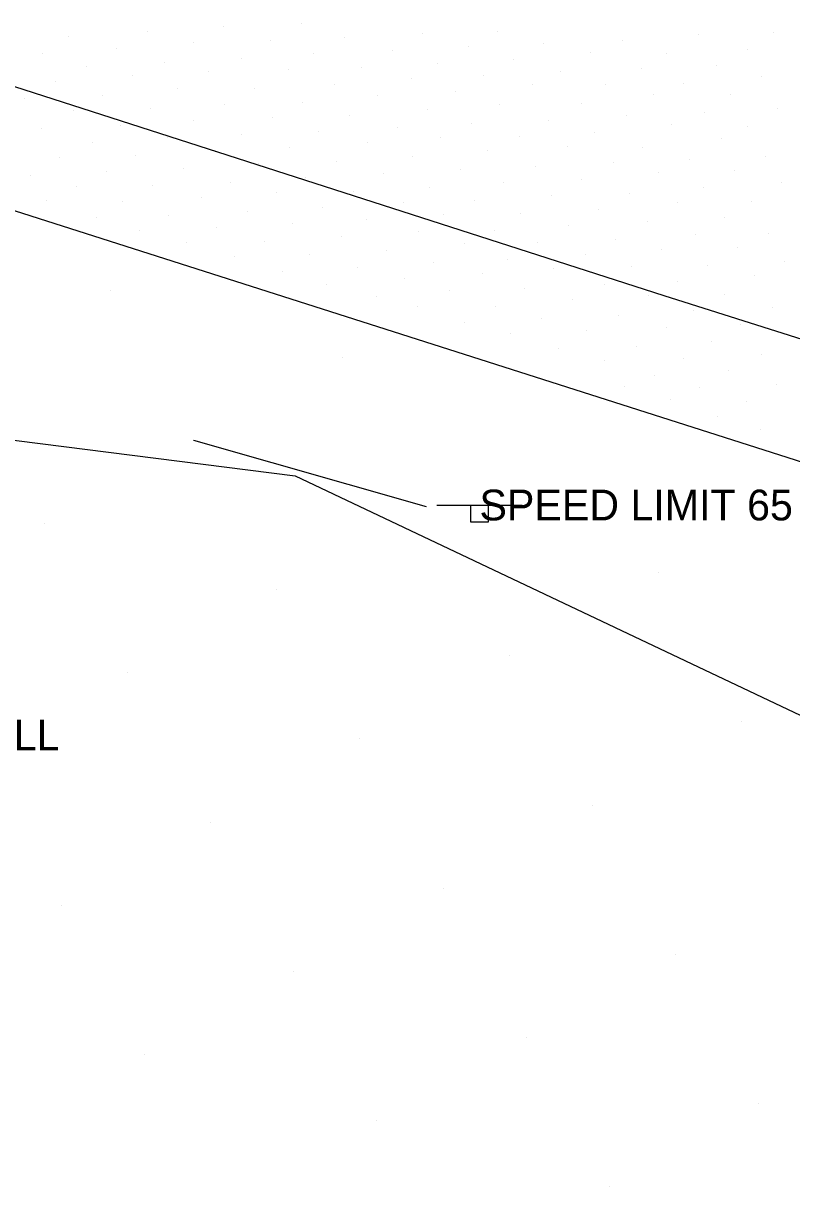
# Model space of a CAD drawing. Extents: x 1733582 to 1734070, y 467256 to 468256.
# Drawn here: x 1733871.5 to 1733916.4, y 467626.2 to 467694.3 of the extents above; entities that cross this region are included whole.
import ezdxf

# ---------------------------------------------------------------- set-up
doc = ezdxf.new("R2010")
doc.units = 0
for name, color, linetype in [('Default', 7, 'Continuous'), ('S_Ground_LevelString', 7, 'Continuous'), ('S_Ground_SpotElevation', 7, 'Continuous'), ('S_Roadway_Edge_Pavement', 7, 'Continuous'), ('S_Roadway_Painted_Lines', 7, 'Continuous'), ('S_Text', 7, 'Continuous'), ('S_Traffic_Sign_SinglePost', 7, 'Continuous'), ('S_Trees_Bush_Line', 7, 'Continuous')]:
    doc.layers.add(name, color=color, linetype=linetype)

# ---------------------------------------------------------------- blocks, each defined once
blk = doc.blocks.new('POINT_DISPLAY')
at = {"layer": 'Default'}
blk.add_line((0, 0), (0, 0), dxfattribs=at)

msp = doc.modelspace()

# ---------------------------------------------------------------- linework, layer by layer
at = {"layer": 'S_Ground_LevelString'}
msp.add_line((1733881.425, 467669.895), (1733895.026, 467666.023), dxfattribs=at)
at = {"layer": 'S_Roadway_Edge_Pavement'}
msp.add_lwpolyline([(1733586.071, 467770.749), (1733667.71, 467746.624), (1733748.731, 467721.817), (1733825.312, 467697.928), (1733923.075, 467666.68), (1733975.856, 467650.261), (1734036.534, 467629.484)], dxfattribs=at)
at = {"layer": 'S_Roadway_Painted_Lines'}
msp.add_lwpolyline([(1733588.359, 467777.226), (1733663.015, 467755.304), (1733706.127, 467742.598), (1733754.684, 467727.868), (1733796.902, 467714.64), (1733820.732, 467706.9), (1733859.007, 467694.431), (1733908.923, 467678.371), (1733969.097, 467659.316), (1734007.606, 467646.911), (1734038.438, 467636.916)], dxfattribs=at)
at = {"layer": 'S_Traffic_Sign_SinglePost'}
msp.add_line((1733895.655, 467666.104), (1733900.645, 467666.104), dxfattribs=at)
msp.add_lwpolyline([(1733897.651, 467666.104), (1733898.649, 467666.104), (1733898.649, 467665.106), (1733897.651, 467665.106)], close=True, dxfattribs=at)
at = {"layer": 'S_Trees_Bush_Line'}
msp.add_lwpolyline([(1733870.477, 467392.586), (1733863.304, 467396.173), (1733858.349, 467437.262), (1733858.746, 467475.792), (1733855.851, 467518.527), (1733851.718, 467552.624), (1733854.117, 467581.29), (1733854.359, 467608.625), (1733855.003, 467643.492), (1733857.771, 467661.204), (1733862.914, 467670.922), (1733887.365, 467667.82), (1733924.768, 467650.09), (1734031.288, 467613.464)], dxfattribs=at)

# ---------------------------------------------------------------- block references
at = {"layer": 'S_Ground_SpotElevation'}
for p in [(1733883.158, 467694.075), (1733887.752, 467694.258), (1733874.118, 467693.543), (1733878.744, 467693.787), (1733881.409, 467693.167), (1733885.912, 467693.265), (1733890.233, 467693.48), (1733894.811, 467693.668), (1733899.217, 467693.829), (1733906.508, 467693.275), (1733910.945, 467693.604), (1733915.355, 467693.753), (1733872.568, 467692.537), (1733876.935, 467692.801), (1733888.432, 467692.53), (1733893.082, 467692.705), (1733897.49, 467692.951), (1733901.914, 467693.092), (1733904.638, 467692.599), (1733909.094, 467692.524), (1733913.83, 467692.758), (1733879.703, 467691.993), (1733884.254, 467692.232), (1733895.697, 467691.92), (1733900.157, 467692.148), (1733912.033, 467691.843), (1733875.151, 467691.779), (1733877.859, 467691.249), (1733882.327, 467691.446), (1733886.956, 467691.566), (1733891.239, 467691.696), (1733898.385, 467691.232), (1733902.914, 467691.458), (1733907.615, 467691.629), (1733914.647, 467691.174), (1733873.365, 467690.88), (1733880.499, 467690.449), (1733885.015, 467690.487), (1733889.69, 467690.725), (1733894.181, 467691.03), (1733901.275, 467690.696), (1733905.533, 467690.715), (1733910.108, 467690.741), (1733871.553, 467689.893), (1733876.122, 467690.074), (1733892.204, 467690.079), (1733896.727, 467690.327), (1733908.332, 467690.097), (1733912.839, 467690.122), (1733874.434, 467689.197), (1733878.916, 467689.295), (1733883.235, 467689.554), (1733887.798, 467689.681), (1733895.105, 467689.247), (1733899.331, 467689.549), (1733904.092, 467689.58), (1733915.561, 467689.302), (1733881.454, 467688.606), (1733886.033, 467688.751), (1733890.571, 467688.905), (1733897.693, 467688.4), (1733902.159, 467688.59), (1733906.72, 467688.901), (1733909.401, 467688.391), (1733911.304, 467689.061), (1733872.546, 467688.146), (1733877.128, 467688.328), (1733884.252, 467687.809), (1733888.763, 467687.942), (1733893.328, 467688.182), (1733904.882, 467687.906), (1733913.834, 467688.276), (1733875.547, 467687.336), (1733879.898, 467687.593), (1733887.018, 467687.032), (1733891.629, 467687.304), (1733895.844, 467687.583), (1733900.488, 467687.691), (1733903.299, 467687.109), (1733907.66, 467687.04), (1733912.3, 467687.544), (1733873.58, 467686.45), (1733878.041, 467686.558), (1733882.692, 467686.774), (1733894.259, 467686.474), (1733898.594, 467686.82), (1733914.858, 467686.516), (1733880.846, 467685.792), (1733885.2, 467686.057), (1733889.79, 467686.206), (1733897.048, 467685.74), (1733901.417, 467685.881), (1733905.987, 467686.141), (1733910.407, 467686.291), (1733913.037, 467685.692), (1733871.906, 467685.394), (1733876.318, 467685.642), (1733883.608, 467684.996), (1733887.978, 467685.253), (1733892.534, 467685.52), (1733899.556, 467684.988), (1733904.131, 467685.145), (1733908.618, 467685.557), (1733915.79, 467684.983), (1733874.578, 467684.736), (1733879.048, 467684.826), (1733886.254, 467684.387), (1733890.802, 467684.436), (1733895.204, 467684.702), (1733906.913, 467684.314), (1733911.264, 467684.67), (1733872.806, 467683.909), (1733877.252, 467683.891), (1733881.874, 467684.1), (1733893.699, 467683.823), (1733897.855, 467683.919), (1733902.344, 467684.238), (1733909.703, 467683.801), (1733914.086, 467683.889), (1733875.748, 467682.946), (1733879.988, 467683.065), (1733884.598, 467683.282), (1733888.96, 467683.492), (1733896.046, 467683.114), (1733900.573, 467683.153), (1733905.119, 467683.406), (1733882.768, 467682.314), (1733887.226, 467682.601), (1733891.569, 467682.838), (1733903.375, 467682.468), (1733907.987, 467682.72), (1733912.489, 467682.926), (1733878.259, 467682.182), (1733890.1, 467681.796), (1733894.596, 467682.092), (1733899.018, 467682.158), (1733906.083, 467681.62), (1733910.77, 467681.915), (1733915.034, 467682.012), (1733881.02, 467681.441), (1733885.601, 467681.529), (1733892.72, 467680.968), (1733897.281, 467681.383), (1733901.549, 467681.475), (1733908.778, 467681.047), (1733913.233, 467681.154), (1733883.806, 467680.624), (1733888.204, 467680.777), (1733895.453, 467680.265), (1733899.78, 467680.474), (1733904.356, 467680.769), (1733915.978, 467680.343), (1733886.633, 467679.786), (1733891.041, 467680.001), (1733898.298, 467679.658), (1733902.485, 467679.919), (1733907.018, 467680.049), (1733911.499, 467680.114), (1733889.184, 467679.013), (1733893.761, 467679.342), (1733905.465, 467678.986), (1733909.749, 467679.166), (1733914.209, 467679.527), (1733876.56, 467678.632), (1733892.115, 467678.297), (1733896.374, 467678.634), (1733900.775, 467678.744), (1733908.045, 467678.359), (1733912.504, 467678.43), (1733894.523, 467677.726), (1733899.067, 467677.699), (1733903.579, 467678.143), (1733910.644, 467677.512), (1733915.263, 467677.636), (1733901.793, 467677.033), (1733906.288, 467677.204), (1733897.271, 467676.782), (1733899.947, 467676.145), (1733904.43, 467676.294), (1733909.101, 467676.466), (1733913.391, 467676.654), (1733911.701, 467675.67), (1733890.161, 467674.76), (1733902.763, 467675.246), (1733907.357, 467675.371), (1733914.655, 467674.926), (1733905.478, 467674.541), (1733910.089, 467674.677), (1733908.413, 467673.678), (1733912.708, 467673.981), (1733906.644, 467673.02), (1733911.01, 467672.98), (1733915.495, 467673.153), (1733909.323, 467672.266), (1733913.739, 467672.134), (1733912.085, 467671.31), (1733914.571, 467670.525), (1733881.425, 467669.895), (1733895.026, 467666.023), (1733872.688, 467665.03), (1733908.628, 467662.151), (1733886.29, 467661.158), (1733899.891, 467657.286), (1733877.553, 467656.293), (1733913.493, 467653.414), (1733891.155, 467652.421), (1733904.756, 467648.549), (1733882.418, 467647.556), (1733896.02, 467643.684), (1733873.681, 467642.691), (1733909.621, 467639.812), (1733887.283, 467638.819), (1733900.885, 467634.947), (1733878.546, 467633.954), (1733914.486, 467631.076), (1733892.148, 467630.082), (1733905.75, 467626.211)]:
    msp.add_blockref('POINT_DISPLAY', p, dxfattribs=at)

# ---------------------------------------------------------------- texts
at = {"layer": 'S_Text'}
for s, p in [('SPEED LIMIT 65', (1733898.15, 467665.204)), ('TOP BRIDGE WALL', (1733851.523, 467651.754))]:
    msp.add_text(s, height=1.8, dxfattribs=at).set_placement(p)

doc.saveas('drawing.dxf')
